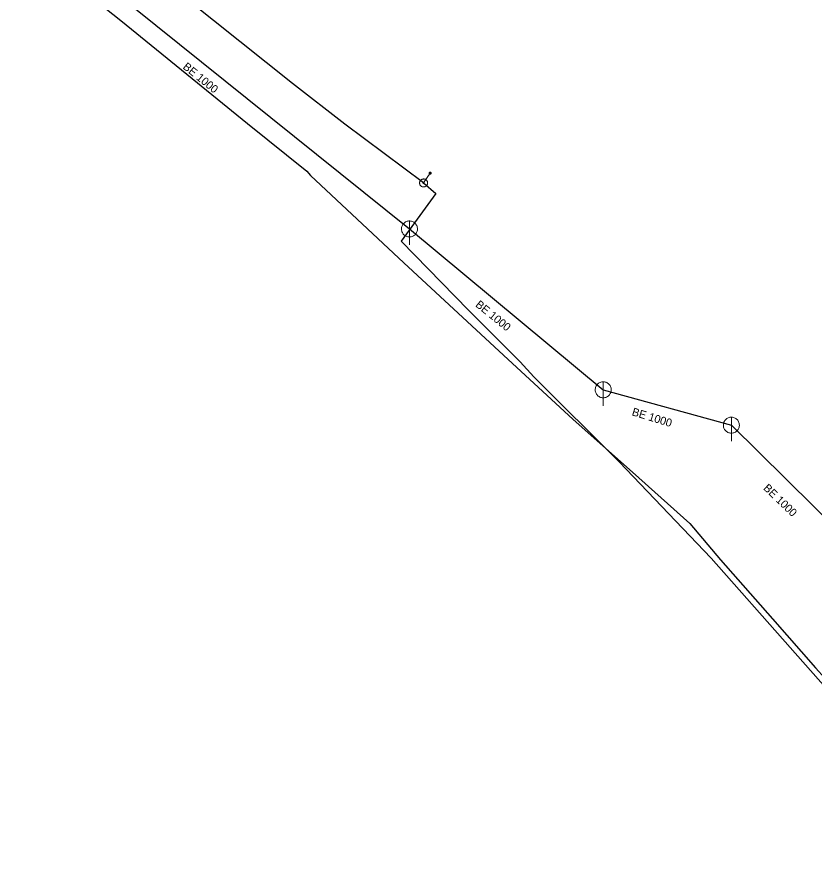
# Model space of a CAD drawing. Extents: x -807203 to -805207, y -993656 to -992505.
# Drawn here: x -806439.5 to -806339.8, y -993001.2 to -992895 of the extents above; entities that cross this region are included whole.
import ezdxf

# ---------------------------------------------------------------- set-up
doc = ezdxf.new("R2010")
doc.units = 0
doc.header["$LTSCALE"] = 0.4
for name, color, linetype, lineweight in [('1', 7, 'Continuous', 13), ('14', 7, 'Continuous', 25), ('17', 7, 'Continuous', 25), ('22', 7, 'Continuous', 13), ('47', 7, 'Continuous', 13), ('9', 7, 'Continuous', 13)]:
    doc.layers.add(name, color=color, linetype=linetype, lineweight=lineweight)

msp = doc.modelspace()

# ---------------------------------------------------------------- linework, layer by layer
at = {"layer": '14', "lineweight": 13}
msp.add_line((-806388.717, -992915.707), (-806387.893, -992914.476), dxfattribs=at)
at = {"layer": '14'}
msp.add_lwpolyline([(-806439.491, -992882.042), (-806390.48, -992921.449), (-806366.285, -992941.529), (-806350.28, -992945.949), (-806336.559, -992959.469), (-806296.91, -993006.629), (-806254.43, -993051.92)], dxfattribs=at)
at = {"layer": '17'}
for points in [[(-806388.717, -992915.707), (-806398.552, -992908.37), (-806405.099, -992903.291), (-806431.594, -992882.078)], [(-806436.941, -992887.123), (-806426.546, -992895.427), (-806410.702, -992908.298), (-806403.285, -992914.215), (-806402.857, -992914.754), (-806391.193, -992925.692), (-806378.734, -992937.224), (-806370.048, -992945.254), (-806362.636, -992951.833), (-806355.477, -992958.243), (-806351.647, -992962.778), (-806345.155, -992970.14), (-806339.761, -992976.258), (-806328.906, -992988.261), (-806292.949, -993029.767), (-806263.022, -993062.39), (-806260.066, -993064.828)], [(-806388.717, -992915.707), (-806387.19, -992917.022), (-806391.53, -992922.958), (-806383.09, -992931.6), (-806376.668, -992938.044), (-806374.927, -992939.932), (-806364.305, -992950.53), (-806352.802, -992962.539), (-806264, -993062.975)]]:
    msp.add_lwpolyline(points, dxfattribs=at)
at = {"layer": '22'}
for p, q in [((-806390.48, -992923.449), (-806390.479, -992920.449)), ((-806366.285, -992943.529), (-806366.284, -992940.529)), ((-806350.28, -992947.949), (-806350.279, -992944.949))]:
    msp.add_line(p, q, dxfattribs=at)
for points in [[(-806389.48, -992921.449), (-806389.485, -992921.34), (-806389.503, -992921.232), (-806389.533, -992921.126), (-806389.573, -992921.025), (-806389.625, -992920.928), (-806389.687, -992920.838), (-806389.759, -992920.755), (-806389.839, -992920.681), (-806389.927, -992920.615), (-806390.021, -992920.56), (-806390.121, -992920.515), (-806390.226, -992920.482), (-806390.333, -992920.46), (-806390.442, -992920.45), (-806390.552, -992920.452), (-806390.66, -992920.466), (-806390.767, -992920.491), (-806390.87, -992920.528), (-806390.968, -992920.577), (-806391.06, -992920.635), (-806391.146, -992920.704), (-806391.223, -992920.781), (-806391.292, -992920.867), (-806391.351, -992920.959), (-806391.399, -992921.057), (-806391.436, -992921.16), (-806391.462, -992921.267), (-806391.476, -992921.375), (-806391.479, -992921.485), (-806391.469, -992921.594), (-806391.448, -992921.701), (-806391.414, -992921.805), (-806391.37, -992921.905), (-806391.315, -992922), (-806391.249, -992922.088), (-806391.175, -992922.168), (-806391.092, -992922.24), (-806391.002, -992922.302), (-806390.906, -992922.354), (-806390.804, -992922.395), (-806390.699, -992922.425), (-806390.591, -992922.443), (-806390.481, -992922.449), (-806390.372, -992922.443), (-806390.264, -992922.425), (-806390.159, -992922.396), (-806390.057, -992922.355), (-806389.96, -992922.303), (-806389.87, -992922.241), (-806389.787, -992922.17), (-806389.712, -992922.09), (-806389.647, -992922.002), (-806389.591, -992921.908), (-806389.547, -992921.808), (-806389.513, -992921.704), (-806389.491, -992921.596), (-806389.481, -992921.487)], [(-806365.285, -992941.529), (-806365.29, -992941.42), (-806365.308, -992941.312), (-806365.338, -992941.206), (-806365.378, -992941.105), (-806365.43, -992941.008), (-806365.492, -992940.918), (-806365.564, -992940.835), (-806365.644, -992940.761), (-806365.732, -992940.695), (-806365.826, -992940.64), (-806365.926, -992940.595), (-806366.031, -992940.562), (-806366.138, -992940.54), (-806366.247, -992940.53), (-806366.357, -992940.532), (-806366.465, -992940.546), (-806366.572, -992940.571), (-806366.675, -992940.608), (-806366.773, -992940.657), (-806366.865, -992940.715), (-806366.951, -992940.784), (-806367.028, -992940.861), (-806367.097, -992940.947), (-806367.156, -992941.039), (-806367.204, -992941.137), (-806367.241, -992941.24), (-806367.267, -992941.347), (-806367.281, -992941.455), (-806367.284, -992941.565), (-806367.274, -992941.674), (-806367.253, -992941.781), (-806367.219, -992941.885), (-806367.175, -992941.985), (-806367.12, -992942.08), (-806367.054, -992942.168), (-806366.98, -992942.248), (-806366.897, -992942.32), (-806366.807, -992942.382), (-806366.711, -992942.434), (-806366.609, -992942.475), (-806366.504, -992942.505), (-806366.396, -992942.523), (-806366.286, -992942.529), (-806366.177, -992942.523), (-806366.069, -992942.505), (-806365.964, -992942.476), (-806365.862, -992942.435), (-806365.765, -992942.383), (-806365.675, -992942.321), (-806365.592, -992942.25), (-806365.517, -992942.17), (-806365.452, -992942.082), (-806365.396, -992941.988), (-806365.352, -992941.888), (-806365.318, -992941.784), (-806365.296, -992941.676), (-806365.286, -992941.567)], [(-806349.28, -992945.949), (-806349.285, -992945.84), (-806349.303, -992945.732), (-806349.333, -992945.626), (-806349.373, -992945.525), (-806349.425, -992945.428), (-806349.487, -992945.338), (-806349.559, -992945.255), (-806349.639, -992945.181), (-806349.727, -992945.115), (-806349.821, -992945.06), (-806349.921, -992945.015), (-806350.026, -992944.982), (-806350.133, -992944.96), (-806350.242, -992944.95), (-806350.352, -992944.952), (-806350.46, -992944.966), (-806350.567, -992944.991), (-806350.67, -992945.028), (-806350.768, -992945.077), (-806350.86, -992945.135), (-806350.946, -992945.204), (-806351.023, -992945.281), (-806351.092, -992945.367), (-806351.151, -992945.459), (-806351.199, -992945.557), (-806351.236, -992945.66), (-806351.262, -992945.767), (-806351.276, -992945.875), (-806351.279, -992945.985), (-806351.269, -992946.094), (-806351.248, -992946.201), (-806351.214, -992946.305), (-806351.17, -992946.405), (-806351.115, -992946.5), (-806351.049, -992946.588), (-806350.975, -992946.668), (-806350.892, -992946.74), (-806350.802, -992946.802), (-806350.706, -992946.854), (-806350.604, -992946.895), (-806350.499, -992946.925), (-806350.391, -992946.943), (-806350.281, -992946.949), (-806350.172, -992946.943), (-806350.064, -992946.925), (-806349.959, -992946.896), (-806349.857, -992946.855), (-806349.76, -992946.803), (-806349.67, -992946.741), (-806349.587, -992946.67), (-806349.512, -992946.59), (-806349.447, -992946.502), (-806349.391, -992946.408), (-806349.347, -992946.308), (-806349.313, -992946.204), (-806349.291, -992946.096), (-806349.281, -992945.987)]]:
    msp.add_lwpolyline(points, close=True, dxfattribs=at)
at = {"layer": '47'}
for points in [[(-806388.337, -992916.033), (-806388.306, -992915.991), (-806388.278, -992915.946), (-806388.256, -992915.899), (-806388.238, -992915.851), (-806388.225, -992915.799), (-806388.218, -992915.747), (-806388.217, -992915.695), (-806388.221, -992915.643), (-806388.23, -992915.592), (-806388.245, -992915.541), (-806388.265, -992915.492), (-806388.29, -992915.447), (-806388.319, -992915.404), (-806388.353, -992915.364), (-806388.39, -992915.327), (-806388.432, -992915.296), (-806388.477, -992915.268), (-806388.524, -992915.245), (-806388.572, -992915.228), (-806388.624, -992915.215), (-806388.676, -992915.208), (-806388.729, -992915.207), (-806388.781, -992915.211), (-806388.832, -992915.22), (-806388.882, -992915.235), (-806388.931, -992915.255), (-806388.977, -992915.279), (-806389.019, -992915.309), (-806389.059, -992915.343), (-806389.096, -992915.38), (-806389.127, -992915.422), (-806389.155, -992915.467), (-806389.178, -992915.514), (-806389.195, -992915.562), (-806389.208, -992915.614), (-806389.215, -992915.665), (-806389.217, -992915.718), (-806389.213, -992915.77), (-806389.203, -992915.822), (-806389.188, -992915.872), (-806389.168, -992915.921), (-806389.144, -992915.966), (-806389.114, -992916.009), (-806389.08, -992916.049), (-806389.043, -992916.086), (-806389.001, -992916.117), (-806388.956, -992916.145), (-806388.91, -992916.168), (-806388.861, -992916.185), (-806388.809, -992916.198), (-806388.758, -992916.205), (-806388.706, -992916.206), (-806388.654, -992916.202), (-806388.602, -992916.193), (-806388.551, -992916.178), (-806388.502, -992916.158), (-806388.457, -992916.134), (-806388.414, -992916.104), (-806388.374, -992916.07)], [(-806388.654, -992915.76), (-806388.648, -992915.753), (-806388.645, -992915.746), (-806388.641, -992915.738), (-806388.638, -992915.73), (-806388.636, -992915.722), (-806388.635, -992915.713), (-806388.634, -992915.705), (-806388.635, -992915.696), (-806388.637, -992915.688), (-806388.639, -992915.679), (-806388.643, -992915.671), (-806388.647, -992915.664), (-806388.651, -992915.657), (-806388.656, -992915.65), (-806388.663, -992915.644), (-806388.67, -992915.638), (-806388.677, -992915.635), (-806388.685, -992915.631), (-806388.693, -992915.628), (-806388.701, -992915.626), (-806388.71, -992915.625), (-806388.718, -992915.624), (-806388.727, -992915.625), (-806388.736, -992915.626), (-806388.744, -992915.629), (-806388.752, -992915.633), (-806388.759, -992915.637), (-806388.766, -992915.641), (-806388.773, -992915.646), (-806388.779, -992915.653), (-806388.785, -992915.66), (-806388.788, -992915.667), (-806388.792, -992915.675), (-806388.795, -992915.683), (-806388.797, -992915.691), (-806388.799, -992915.699), (-806388.799, -992915.708), (-806388.798, -992915.717), (-806388.797, -992915.726), (-806388.794, -992915.734), (-806388.79, -992915.742), (-806388.786, -992915.749), (-806388.782, -992915.756), (-806388.777, -992915.763), (-806388.77, -992915.769), (-806388.763, -992915.775), (-806388.756, -992915.778), (-806388.748, -992915.782), (-806388.74, -992915.785), (-806388.732, -992915.787), (-806388.724, -992915.789), (-806388.715, -992915.789), (-806388.706, -992915.788), (-806388.698, -992915.786), (-806388.689, -992915.784), (-806388.681, -992915.78), (-806388.674, -992915.776), (-806388.667, -992915.772), (-806388.66, -992915.767)]]:
    msp.add_lwpolyline(points, close=True, dxfattribs=at)
at = {"layer": '9'}
for points in [[(-806388.019, -992914.476), (-806388.019, -992914.489), (-806388.017, -992914.502), (-806388.014, -992914.515), (-806388.009, -992914.527), (-806388.003, -992914.539), (-806387.996, -992914.55), (-806387.988, -992914.56), (-806387.978, -992914.57), (-806387.968, -992914.578), (-806387.957, -992914.585), (-806387.945, -992914.591), (-806387.933, -992914.596), (-806387.92, -992914.599), (-806387.907, -992914.601), (-806387.894, -992914.603), (-806387.881, -992914.602), (-806387.868, -992914.6), (-806387.855, -992914.597), (-806387.843, -992914.592), (-806387.831, -992914.586), (-806387.82, -992914.579), (-806387.81, -992914.571), (-806387.8, -992914.561), (-806387.792, -992914.551), (-806387.785, -992914.54), (-806387.779, -992914.528), (-806387.774, -992914.516), (-806387.771, -992914.503), (-806387.769, -992914.49), (-806387.767, -992914.477), (-806387.768, -992914.464), (-806387.77, -992914.451), (-806387.773, -992914.438), (-806387.778, -992914.426), (-806387.784, -992914.414), (-806387.791, -992914.403), (-806387.799, -992914.393), (-806387.809, -992914.383), (-806387.819, -992914.375), (-806387.83, -992914.368), (-806387.842, -992914.362), (-806387.854, -992914.357), (-806387.867, -992914.354), (-806387.88, -992914.352), (-806387.893, -992914.351), (-806387.906, -992914.351), (-806387.919, -992914.353), (-806387.932, -992914.356), (-806387.944, -992914.361), (-806387.956, -992914.367), (-806387.967, -992914.374), (-806387.977, -992914.382), (-806387.987, -992914.392), (-806387.995, -992914.402), (-806388.002, -992914.413), (-806388.008, -992914.425), (-806388.013, -992914.437), (-806388.016, -992914.45), (-806388.018, -992914.463)], [(-806387.999, -992914.476), (-806388, -992914.487), (-806387.998, -992914.498), (-806387.995, -992914.509), (-806387.991, -992914.519), (-806387.986, -992914.529), (-806387.98, -992914.538), (-806387.973, -992914.547), (-806387.965, -992914.555), (-806387.956, -992914.562), (-806387.947, -992914.568), (-806387.937, -992914.573), (-806387.927, -992914.577), (-806387.916, -992914.58), (-806387.905, -992914.583), (-806387.894, -992914.583), (-806387.883, -992914.583), (-806387.872, -992914.581), (-806387.861, -992914.578), (-806387.851, -992914.574), (-806387.841, -992914.569), (-806387.832, -992914.563), (-806387.823, -992914.556), (-806387.815, -992914.548), (-806387.808, -992914.539), (-806387.802, -992914.53), (-806387.797, -992914.52), (-806387.793, -992914.51), (-806387.79, -992914.499), (-806387.788, -992914.488), (-806387.787, -992914.477), (-806387.787, -992914.466), (-806387.789, -992914.455), (-806387.792, -992914.444), (-806387.796, -992914.434), (-806387.801, -992914.424), (-806387.807, -992914.415), (-806387.814, -992914.406), (-806387.822, -992914.398), (-806387.831, -992914.391), (-806387.84, -992914.385), (-806387.85, -992914.38), (-806387.86, -992914.376), (-806387.871, -992914.373), (-806387.882, -992914.371), (-806387.893, -992914.371), (-806387.904, -992914.37), (-806387.915, -992914.372), (-806387.926, -992914.375), (-806387.936, -992914.379), (-806387.946, -992914.384), (-806387.955, -992914.39), (-806387.964, -992914.397), (-806387.972, -992914.405), (-806387.979, -992914.414), (-806387.985, -992914.423), (-806387.99, -992914.433), (-806387.994, -992914.443), (-806387.997, -992914.454), (-806387.999, -992914.465)], [(-806387.98, -992914.476), (-806387.98, -992914.485), (-806387.979, -992914.494), (-806387.976, -992914.503), (-806387.973, -992914.511), (-806387.969, -992914.519), (-806387.964, -992914.527), (-806387.958, -992914.534), (-806387.952, -992914.54), (-806387.945, -992914.546), (-806387.937, -992914.551), (-806387.929, -992914.555), (-806387.921, -992914.558), (-806387.912, -992914.561), (-806387.903, -992914.562), (-806387.894, -992914.564), (-806387.885, -992914.563), (-806387.876, -992914.562), (-806387.867, -992914.559), (-806387.859, -992914.556), (-806387.851, -992914.552), (-806387.843, -992914.547), (-806387.836, -992914.541), (-806387.83, -992914.535), (-806387.824, -992914.528), (-806387.819, -992914.52), (-806387.815, -992914.512), (-806387.812, -992914.504), (-806387.809, -992914.495), (-806387.808, -992914.486), (-806387.806, -992914.477), (-806387.807, -992914.468), (-806387.808, -992914.459), (-806387.811, -992914.45), (-806387.814, -992914.442), (-806387.818, -992914.434), (-806387.823, -992914.426), (-806387.829, -992914.419), (-806387.835, -992914.413), (-806387.842, -992914.407), (-806387.85, -992914.402), (-806387.858, -992914.398), (-806387.866, -992914.395), (-806387.875, -992914.392), (-806387.884, -992914.391), (-806387.893, -992914.39), (-806387.902, -992914.39), (-806387.911, -992914.391), (-806387.92, -992914.394), (-806387.928, -992914.397), (-806387.936, -992914.401), (-806387.944, -992914.406), (-806387.951, -992914.412), (-806387.957, -992914.418), (-806387.963, -992914.425), (-806387.968, -992914.433), (-806387.972, -992914.441), (-806387.975, -992914.449), (-806387.978, -992914.458), (-806387.979, -992914.467)], [(-806387.96, -992914.476), (-806387.96, -992914.483), (-806387.959, -992914.49), (-806387.958, -992914.497), (-806387.955, -992914.503), (-806387.952, -992914.509), (-806387.948, -992914.515), (-806387.944, -992914.521), (-806387.939, -992914.526), (-806387.933, -992914.53), (-806387.927, -992914.534), (-806387.921, -992914.537), (-806387.915, -992914.54), (-806387.908, -992914.541), (-806387.901, -992914.544), (-806387.894, -992914.544), (-806387.887, -992914.544), (-806387.88, -992914.542), (-806387.873, -992914.541), (-806387.867, -992914.538), (-806387.86, -992914.535), (-806387.855, -992914.531), (-806387.849, -992914.527), (-806387.844, -992914.522), (-806387.84, -992914.516), (-806387.836, -992914.51), (-806387.833, -992914.504), (-806387.83, -992914.498), (-806387.828, -992914.491), (-806387.827, -992914.484), (-806387.826, -992914.477), (-806387.826, -992914.47), (-806387.827, -992914.463), (-806387.829, -992914.456), (-806387.832, -992914.45), (-806387.835, -992914.443), (-806387.839, -992914.438), (-806387.843, -992914.432), (-806387.848, -992914.427), (-806387.854, -992914.423), (-806387.859, -992914.419), (-806387.866, -992914.416), (-806387.872, -992914.413), (-806387.879, -992914.411), (-806387.886, -992914.41), (-806387.893, -992914.41), (-806387.9, -992914.41), (-806387.907, -992914.41), (-806387.914, -992914.412), (-806387.92, -992914.415), (-806387.926, -992914.418), (-806387.932, -992914.422), (-806387.938, -992914.426), (-806387.943, -992914.431), (-806387.947, -992914.437), (-806387.951, -992914.442), (-806387.954, -992914.449), (-806387.957, -992914.455), (-806387.958, -992914.462), (-806387.96, -992914.469)], [(-806387.94, -992914.476), (-806387.94, -992914.481), (-806387.94, -992914.486), (-806387.939, -992914.491), (-806387.937, -992914.495), (-806387.935, -992914.5), (-806387.932, -992914.504), (-806387.929, -992914.507), (-806387.925, -992914.511), (-806387.922, -992914.514), (-806387.918, -992914.517), (-806387.913, -992914.519), (-806387.909, -992914.521), (-806387.904, -992914.522), (-806387.899, -992914.524), (-806387.894, -992914.524), (-806387.889, -992914.524), (-806387.884, -992914.523), (-806387.879, -992914.522), (-806387.875, -992914.52), (-806387.87, -992914.518), (-806387.866, -992914.515), (-806387.862, -992914.512), (-806387.859, -992914.508), (-806387.856, -992914.505), (-806387.853, -992914.501), (-806387.851, -992914.496), (-806387.849, -992914.492), (-806387.848, -992914.487), (-806387.847, -992914.482), (-806387.846, -992914.477), (-806387.846, -992914.472), (-806387.847, -992914.467), (-806387.848, -992914.462), (-806387.85, -992914.458), (-806387.852, -992914.453), (-806387.855, -992914.449), (-806387.858, -992914.445), (-806387.861, -992914.442), (-806387.865, -992914.439), (-806387.869, -992914.436), (-806387.874, -992914.434), (-806387.878, -992914.432), (-806387.883, -992914.431), (-806387.888, -992914.43), (-806387.893, -992914.43), (-806387.898, -992914.43), (-806387.903, -992914.431), (-806387.908, -992914.431), (-806387.912, -992914.433), (-806387.917, -992914.435), (-806387.921, -992914.438), (-806387.924, -992914.441), (-806387.928, -992914.444), (-806387.931, -992914.448), (-806387.934, -992914.452), (-806387.936, -992914.457), (-806387.938, -992914.461), (-806387.939, -992914.466), (-806387.94, -992914.471)], [(-806387.92, -992914.476), (-806387.92, -992914.479), (-806387.921, -992914.482), (-806387.92, -992914.484), (-806387.919, -992914.487), (-806387.918, -992914.49), (-806387.916, -992914.492), (-806387.914, -992914.494), (-806387.912, -992914.496), (-806387.91, -992914.498), (-806387.908, -992914.5), (-806387.905, -992914.502), (-806387.902, -992914.503), (-806387.9, -992914.503), (-806387.897, -992914.504), (-806387.894, -992914.504), (-806387.891, -992914.504), (-806387.888, -992914.504), (-806387.885, -992914.503), (-806387.883, -992914.502), (-806387.88, -992914.501), (-806387.878, -992914.499), (-806387.875, -992914.497), (-806387.873, -992914.495), (-806387.872, -992914.493), (-806387.87, -992914.491), (-806387.869, -992914.488), (-806387.867, -992914.485), (-806387.867, -992914.483), (-806387.866, -992914.48), (-806387.865, -992914.477), (-806387.866, -992914.474), (-806387.866, -992914.471), (-806387.867, -992914.468), (-806387.868, -992914.466), (-806387.869, -992914.463), (-806387.871, -992914.461), (-806387.872, -992914.458), (-806387.874, -992914.456), (-806387.877, -992914.455), (-806387.879, -992914.453), (-806387.882, -992914.452), (-806387.884, -992914.451), (-806387.887, -992914.45), (-806387.89, -992914.45), (-806387.893, -992914.449), (-806387.896, -992914.45), (-806387.899, -992914.449), (-806387.901, -992914.451), (-806387.904, -992914.451), (-806387.907, -992914.452), (-806387.909, -992914.454), (-806387.911, -992914.455), (-806387.913, -992914.457), (-806387.915, -992914.46), (-806387.917, -992914.462), (-806387.918, -992914.465), (-806387.919, -992914.467), (-806387.92, -992914.47), (-806387.92, -992914.473)], [(-806387.901, -992914.476), (-806387.901, -992914.478), (-806387.901, -992914.478), (-806387.9, -992914.478), (-806387.9, -992914.48), (-806387.901, -992914.481), (-806387.899, -992914.481), (-806387.899, -992914.481), (-806387.899, -992914.483), (-806387.899, -992914.483), (-806387.898, -992914.484), (-806387.896, -992914.484), (-806387.896, -992914.484), (-806387.896, -992914.485), (-806387.894, -992914.485), (-806387.894, -992914.485), (-806387.893, -992914.485), (-806387.892, -992914.485), (-806387.892, -992914.484), (-806387.891, -992914.484), (-806387.889, -992914.484), (-806387.889, -992914.483), (-806387.889, -992914.483), (-806387.888, -992914.482), (-806387.888, -992914.482), (-806387.886, -992914.481), (-806387.886, -992914.48), (-806387.885, -992914.479), (-806387.885, -992914.479), (-806387.885, -992914.478), (-806387.885, -992914.477), (-806387.885, -992914.476), (-806387.885, -992914.475), (-806387.885, -992914.475), (-806387.886, -992914.474), (-806387.886, -992914.473), (-806387.887, -992914.472), (-806387.887, -992914.472), (-806387.888, -992914.471), (-806387.888, -992914.471), (-806387.889, -992914.47), (-806387.89, -992914.47), (-806387.891, -992914.469), (-806387.891, -992914.469), (-806387.892, -992914.469), (-806387.893, -992914.469), (-806387.894, -992914.469), (-806387.895, -992914.469), (-806387.895, -992914.469), (-806387.896, -992914.47), (-806387.897, -992914.469), (-806387.898, -992914.471), (-806387.898, -992914.471), (-806387.899, -992914.471), (-806387.899, -992914.471), (-806387.9, -992914.473), (-806387.9, -992914.474), (-806387.9, -992914.475), (-806387.901, -992914.475), (-806387.901, -992914.476)]]:
    msp.add_lwpolyline(points, close=True, dxfattribs=at)

# ---------------------------------------------------------------- texts
at = {"layer": '1'}
for rotation, p in [(321, (-806418.866, -992901.341)), (321, (-806382.325, -992931.051)), (343, (-806362.778, -992944.7)), (316, (-806346.36, -992953.894))]:
    msp.add_text('BE 1000 ', height=1, rotation=rotation, dxfattribs=at).set_placement(p)

doc.saveas('drawing.dxf')
